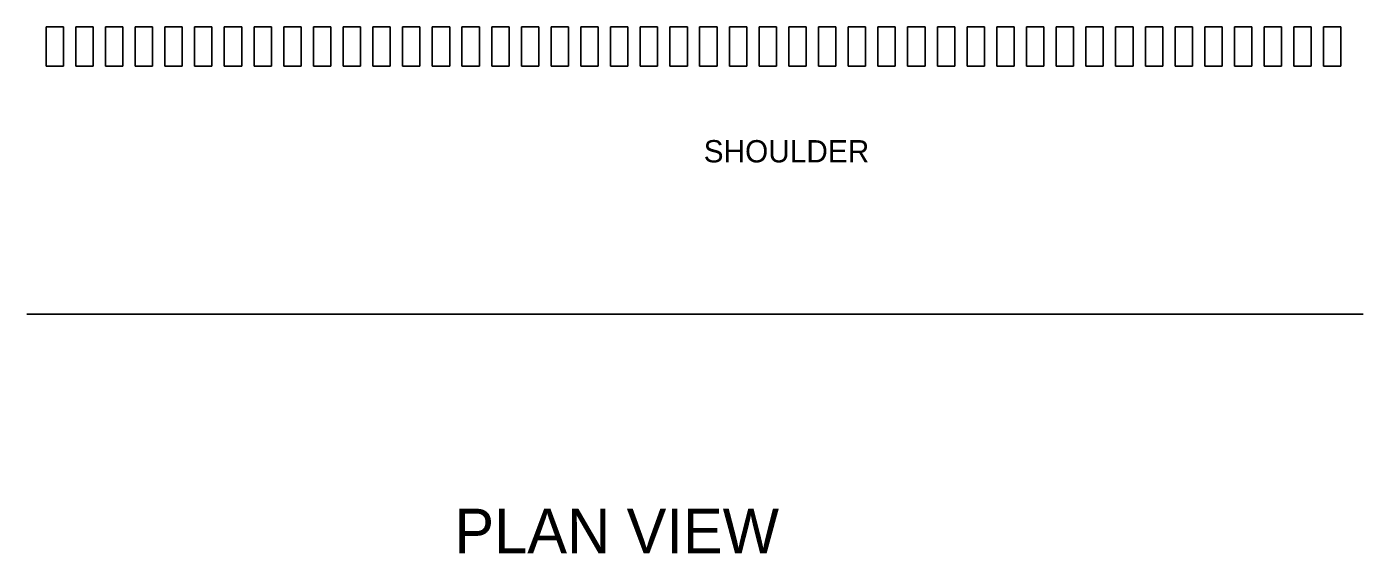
# Model space of a CAD drawing. Extents: x 1929624 to 1936506, y 596315 to 605721.
# Drawn here: x 1933783.1 to 1934143, y 600914.1 to 601055.8 of the extents above; entities that cross this region are included whole.
import ezdxf

# ---------------------------------------------------------------- set-up
doc = ezdxf.new("R2010")
doc.units = 0
doc.layers.add('Default', color=7, linetype='Continuous')

msp = doc.modelspace()

# ---------------------------------------------------------------- linework, layer by layer
at = {"layer": 'Default'}
for p, q in [((1933792.99, 601055.82), (1933788.31, 601055.82)), ((1933788.31, 601055.82), (1933788.31, 601045.18)), ((1933792.99, 601055.82), (1933792.99, 601045.18)), ((1933800.99, 601055.82), (1933796.31, 601055.82)), ((1933796.31, 601055.82), (1933796.31, 601045.18)), ((1933800.99, 601055.82), (1933800.99, 601045.18)), ((1933808.99, 601055.82), (1933804.31, 601055.82)), ((1933804.31, 601055.82), (1933804.31, 601045.18)), ((1933808.99, 601055.82), (1933808.99, 601045.18)), ((1933816.99, 601055.82), (1933812.31, 601055.82)), ((1933812.31, 601055.82), (1933812.31, 601045.18)), ((1933816.99, 601055.82), (1933816.99, 601045.18)), ((1933824.99, 601055.82), (1933820.31, 601055.82)), ((1933820.31, 601055.82), (1933820.31, 601045.18)), ((1933824.99, 601055.82), (1933824.99, 601045.18)), ((1933832.99, 601055.82), (1933828.31, 601055.82)), ((1933828.31, 601055.82), (1933828.31, 601045.18)), ((1933832.99, 601055.82), (1933832.99, 601045.18)), ((1933840.99, 601055.82), (1933836.31, 601055.82)), ((1933836.31, 601055.82), (1933836.31, 601045.18)), ((1933840.99, 601055.82), (1933840.99, 601045.18)), ((1933848.99, 601055.82), (1933844.31, 601055.82)), ((1933844.31, 601055.82), (1933844.31, 601045.18)), ((1933848.99, 601055.82), (1933848.99, 601045.18)), ((1933856.99, 601055.82), (1933852.31, 601055.82)), ((1933852.31, 601055.82), (1933852.31, 601045.18)), ((1933856.99, 601055.82), (1933856.99, 601045.18)), ((1933864.99, 601055.82), (1933860.31, 601055.82)), ((1933860.31, 601055.82), (1933860.31, 601045.18)), ((1933864.99, 601055.82), (1933864.99, 601045.18)), ((1933872.99, 601055.82), (1933868.31, 601055.82)), ((1933868.31, 601055.82), (1933868.31, 601045.18)), ((1933872.99, 601055.82), (1933872.99, 601045.18)), ((1933880.99, 601055.82), (1933876.31, 601055.82)), ((1933876.31, 601055.82), (1933876.31, 601045.18)), ((1933880.99, 601055.82), (1933880.99, 601045.18)), ((1933888.99, 601055.82), (1933884.31, 601055.82)), ((1933884.31, 601055.82), (1933884.31, 601045.18)), ((1933888.99, 601055.82), (1933888.99, 601045.18)), ((1933896.99, 601055.82), (1933892.31, 601055.82)), ((1933892.31, 601055.82), (1933892.31, 601045.18)), ((1933896.99, 601055.82), (1933896.99, 601045.18)), ((1933904.98, 601055.82), (1933900.3, 601055.82)), ((1933900.3, 601055.82), (1933900.3, 601045.18)), ((1933904.98, 601055.82), (1933904.98, 601045.18)), ((1933912.98, 601055.82), (1933908.3, 601055.82)), ((1933908.3, 601055.82), (1933908.3, 601045.18)), ((1933912.98, 601055.82), (1933912.98, 601045.18)), ((1933920.98, 601055.82), (1933916.3, 601055.82)), ((1933916.3, 601055.82), (1933916.3, 601045.18)), ((1933920.98, 601055.82), (1933920.98, 601045.18)), ((1933928.98, 601055.82), (1933924.3, 601055.82)), ((1933924.3, 601055.82), (1933924.3, 601045.18)), ((1933928.98, 601055.82), (1933928.98, 601045.18)), ((1933936.98, 601055.82), (1933932.3, 601055.82)), ((1933932.3, 601055.82), (1933932.3, 601045.18)), ((1933936.98, 601055.82), (1933936.98, 601045.18)), ((1933944.98, 601055.82), (1933940.3, 601055.82)), ((1933940.3, 601055.82), (1933940.3, 601045.18)), ((1933944.98, 601055.82), (1933944.98, 601045.18)), ((1933952.98, 601055.82), (1933948.3, 601055.82)), ((1933948.3, 601055.82), (1933948.3, 601045.18)), ((1933952.98, 601055.82), (1933952.98, 601045.18)), ((1933960.98, 601055.82), (1933956.3, 601055.82)), ((1933956.3, 601055.82), (1933956.3, 601045.18)), ((1933960.98, 601055.82), (1933960.98, 601045.18)), ((1933968.98, 601055.82), (1933964.3, 601055.82)), ((1933964.3, 601055.82), (1933964.3, 601045.18)), ((1933968.98, 601055.82), (1933968.98, 601045.18)), ((1933976.98, 601055.82), (1933972.3, 601055.82)), ((1933972.3, 601055.82), (1933972.3, 601045.18)), ((1933976.98, 601055.82), (1933976.98, 601045.18)), ((1933984.98, 601055.82), (1933980.3, 601055.82)), ((1933980.3, 601055.82), (1933980.3, 601045.18)), ((1933984.98, 601055.82), (1933984.98, 601045.18)), ((1933992.98, 601055.82), (1933988.3, 601055.82)), ((1933988.3, 601055.82), (1933988.3, 601045.18)), ((1933992.98, 601055.82), (1933992.98, 601045.18)), ((1934000.98, 601055.82), (1933996.3, 601055.82)), ((1933996.3, 601055.82), (1933996.3, 601045.18)), ((1934000.98, 601055.82), (1934000.98, 601045.18)), ((1934008.98, 601055.82), (1934004.3, 601055.82)), ((1934004.3, 601055.82), (1934004.3, 601045.18)), ((1934008.98, 601055.82), (1934008.98, 601045.18)), ((1934016.98, 601055.82), (1934012.3, 601055.82)), ((1934012.3, 601055.82), (1934012.3, 601045.18)), ((1934016.98, 601055.82), (1934016.98, 601045.18)), ((1934024.98, 601055.82), (1934020.3, 601055.82)), ((1934020.3, 601055.82), (1934020.3, 601045.18)), ((1934024.98, 601055.82), (1934024.98, 601045.18)), ((1934032.98, 601055.82), (1934028.3, 601055.82)), ((1934028.3, 601055.82), (1934028.3, 601045.18)), ((1934032.98, 601055.82), (1934032.98, 601045.18)), ((1934040.98, 601055.82), (1934036.3, 601055.82)), ((1934036.3, 601055.82), (1934036.3, 601045.18)), ((1934040.98, 601055.82), (1934040.98, 601045.18)), ((1934048.98, 601055.82), (1934044.3, 601055.82)), ((1934044.3, 601055.82), (1934044.3, 601045.18)), ((1934048.98, 601055.82), (1934048.98, 601045.18)), ((1934056.98, 601055.82), (1934052.3, 601055.82)), ((1934052.3, 601055.82), (1934052.3, 601045.18)), ((1934056.98, 601055.82), (1934056.98, 601045.18)), ((1934064.98, 601055.82), (1934060.3, 601055.82)), ((1934060.3, 601055.82), (1934060.3, 601045.18)), ((1934064.98, 601055.82), (1934064.98, 601045.18)), ((1934072.98, 601055.82), (1934068.3, 601055.82)), ((1934068.3, 601055.82), (1934068.3, 601045.18)), ((1934072.98, 601055.82), (1934072.98, 601045.18)), ((1934080.98, 601055.82), (1934076.3, 601055.82)), ((1934076.3, 601055.82), (1934076.3, 601045.18)), ((1934080.98, 601055.82), (1934080.98, 601045.18)), ((1934088.98, 601055.82), (1934084.3, 601055.82)), ((1934084.3, 601055.82), (1934084.3, 601045.18)), ((1934088.98, 601055.82), (1934088.98, 601045.18)), ((1934096.98, 601055.82), (1934092.3, 601055.82)), ((1934092.3, 601055.82), (1934092.3, 601045.18)), ((1934096.98, 601055.82), (1934096.98, 601045.18)), ((1934104.98, 601055.82), (1934100.3, 601055.82)), ((1934100.3, 601055.82), (1934100.3, 601045.18)), ((1934104.98, 601055.82), (1934104.98, 601045.18)), ((1934112.98, 601055.82), (1934108.3, 601055.82)), ((1934108.3, 601055.82), (1934108.3, 601045.18)), ((1934112.98, 601055.82), (1934112.98, 601045.18)), ((1934120.98, 601055.82), (1934116.3, 601055.82)), ((1934116.3, 601055.82), (1934116.3, 601045.18)), ((1934120.98, 601055.82), (1934120.98, 601045.18)), ((1934128.98, 601055.82), (1934124.3, 601055.82)), ((1934124.3, 601055.82), (1934124.3, 601045.18)), ((1934128.98, 601055.82), (1934128.98, 601045.18)), ((1934136.98, 601055.82), (1934132.3, 601055.82)), ((1934132.3, 601055.82), (1934132.3, 601045.18)), ((1934136.98, 601055.82), (1934136.98, 601045.18)), ((1933788.31, 601045.18), (1933792.99, 601045.18)), ((1933796.31, 601045.18), (1933800.99, 601045.18)), ((1933804.31, 601045.18), (1933808.99, 601045.18)), ((1933812.31, 601045.18), (1933816.99, 601045.18)), ((1933820.31, 601045.18), (1933824.99, 601045.18)), ((1933828.31, 601045.18), (1933832.99, 601045.18)), ((1933836.31, 601045.18), (1933840.99, 601045.18)), ((1933844.31, 601045.18), (1933848.99, 601045.18)), ((1933852.31, 601045.18), (1933856.99, 601045.18)), ((1933860.31, 601045.18), (1933864.99, 601045.18)), ((1933868.31, 601045.18), (1933872.99, 601045.18)), ((1933876.31, 601045.18), (1933880.99, 601045.18)), ((1933884.31, 601045.18), (1933888.99, 601045.18)), ((1933892.31, 601045.18), (1933896.99, 601045.18)), ((1933900.3, 601045.18), (1933904.98, 601045.18)), ((1933908.3, 601045.18), (1933912.98, 601045.18)), ((1933916.3, 601045.18), (1933920.98, 601045.18)), ((1933924.3, 601045.18), (1933928.98, 601045.18)), ((1933932.3, 601045.18), (1933936.98, 601045.18)), ((1933940.3, 601045.18), (1933944.98, 601045.18)), ((1933948.3, 601045.18), (1933952.98, 601045.18)), ((1933956.3, 601045.18), (1933960.98, 601045.18)), ((1933964.3, 601045.18), (1933968.98, 601045.18)), ((1933972.3, 601045.18), (1933976.98, 601045.18)), ((1933980.3, 601045.18), (1933984.98, 601045.18)), ((1933988.3, 601045.18), (1933992.98, 601045.18)), ((1933996.3, 601045.18), (1934000.98, 601045.18)), ((1934004.3, 601045.18), (1934008.98, 601045.18)), ((1934012.3, 601045.18), (1934016.98, 601045.18)), ((1934020.3, 601045.18), (1934024.98, 601045.18)), ((1934028.3, 601045.18), (1934032.98, 601045.18)), ((1934036.3, 601045.18), (1934040.98, 601045.18)), ((1934044.3, 601045.18), (1934048.98, 601045.18)), ((1934052.3, 601045.18), (1934056.98, 601045.18)), ((1934060.3, 601045.18), (1934064.98, 601045.18)), ((1934068.3, 601045.18), (1934072.98, 601045.18)), ((1934076.3, 601045.18), (1934080.98, 601045.18)), ((1934084.3, 601045.18), (1934088.98, 601045.18)), ((1934092.3, 601045.18), (1934096.98, 601045.18)), ((1934100.3, 601045.18), (1934104.98, 601045.18)), ((1934108.3, 601045.18), (1934112.98, 601045.18)), ((1934116.3, 601045.18), (1934120.98, 601045.18)), ((1934124.3, 601045.18), (1934128.98, 601045.18)), ((1934132.3, 601045.18), (1934136.98, 601045.18)), ((1933783.11, 600978.48), (1934142.98, 600978.48))]:
    msp.add_line(p, q, dxfattribs=at)

# ---------------------------------------------------------------- texts
for s, height, p in [('SHOULDER', 6, (1933965.38, 601019.3)), ('PLAN VIEW ', 12, (1933898.26, 600914.08))]:
    msp.add_text(s, height=height, dxfattribs=at).set_placement(p)

doc.saveas('drawing.dxf')
